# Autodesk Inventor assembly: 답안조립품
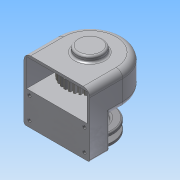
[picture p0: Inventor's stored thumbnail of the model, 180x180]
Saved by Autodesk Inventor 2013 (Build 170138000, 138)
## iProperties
Created: 2015-02
Part Number: 답안조립품
Document SubType Name: Assembly
Designer: Administrator
Author: Administrator
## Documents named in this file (14)
- C:\Documents and Settings\Administrator\바탕 화면\450214V1023\답안조립품.iam
- C:\Documents and Settings\Administrator\바탕 화면\450214V1023\1-본체.ipt
- C:\Documents and Settings\Administrator\바탕 화면\450214V1023\베어링 6001.ipt
- C:\Documents and Settings\Administrator\바탕 화면\450214V1023\축.ipt
- C:\Documents and Settings\Administrator\바탕 화면\450214V1023\키4x4.ipt
- C:\Documents and Settings\Administrator\바탕 화면\450214V1023\키5x5.ipt
- C:\Documents and Settings\Administrator\바탕 화면\450214V1023\5-스퍼기어.ipt
- C:\Documents and Settings\Administrator\바탕 화면\450214V1023\축커버.ipt
- C:\Documents and Settings\Administrator\바탕 화면\450214V1023\오일실.ipt
- C:\Documents and Settings\Administrator\바탕 화면\450214V1023\M3x0.5.ipt
- C:\Documents and Settings\Administrator\바탕 화면\450214V1023\4-V밸트풀리.ipt
- C:\Documents and Settings\Administrator\바탕 화면\450214V1023\와샤.ipt
- C:\Documents and Settings\Administrator\바탕 화면\450214V1023\M5x0.8.ipt
- M5x0.8.ipt
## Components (7 placed, 4 different names)
1. 1-본체:1
2. M3x0.5:1
3. M3x0.5:2
4. M3x0.5:3
5. M3x0.5:4
6. 4-V밸트풀리:1 — 각도:4
7. M5x0.8:1
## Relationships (1: Angle 1)
- 각도:4 [Angle]: 4-V밸트풀리:1
